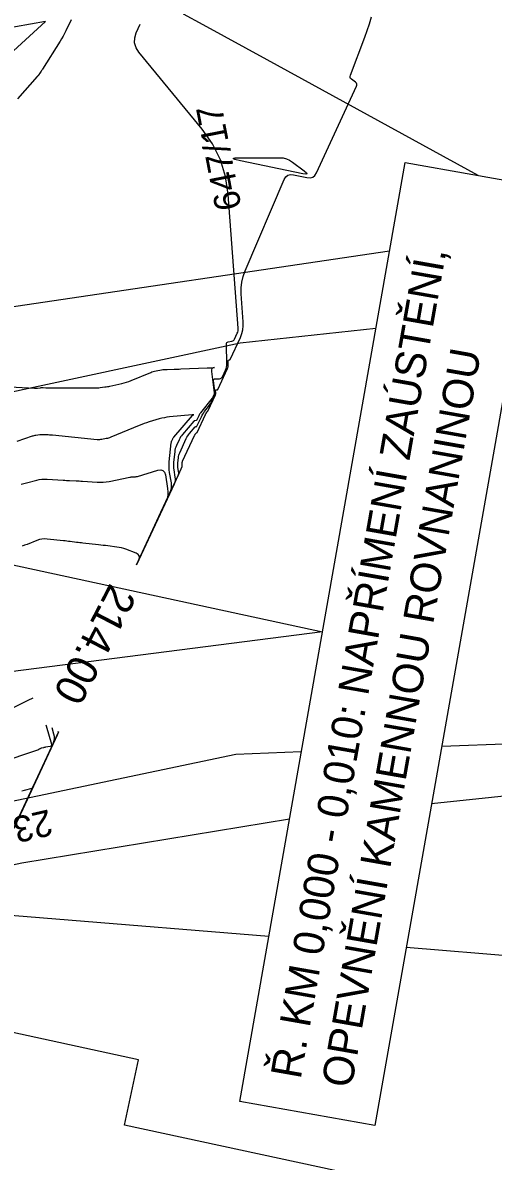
# Model space of a CAD drawing. Extents: x -534481 to -534256, y -1190577 to -1190138.
# Drawn here: x -534390.37 to -534375, y -1190542.27 to -1190505.1 of the extents above; entities that cross this region are included whole.
import ezdxf

# ---------------------------------------------------------------- set-up
doc = ezdxf.new("R2010")
doc.units = 0
for name, color, linetype in [('30', 7, 'Continuous'), ('31', 7, 'Continuous'), ('40', 7, 'Continuous'), ('_N_text', 7, 'Continuous'), ('Hranice parcel', 7, 'Continuous'), ('Parcelní čísla', 7, 'Continuous'), ('Polygon budovy', 7, 'Continuous')]:
    doc.layers.add(name, color=color, linetype=linetype)

msp = doc.modelspace()

# ---------------------------------------------------------------- linework, layer by layer
at = {"layer": '30'}
for points in [[(-534386.653, -1190522.8), (-534385.856, -1190521.088), (-534385.294, -1190519.882), (-534385.282, -1190519.85), (-534385.275, -1190519.818), (-534385.273, -1190519.786), (-534385.276, -1190519.752), (-534385.298, -1190519.617), (-534385.302, -1190519.583), (-534385.305, -1190519.549), (-534385.304, -1190519.515), (-534385.302, -1190519.481), (-534385.284, -1190519.303), (-534385.278, -1190519.263), (-534385.269, -1190519.223), (-534385.257, -1190519.184), (-534385.241, -1190519.146), (-534385.026, -1190518.68), (-534385.004, -1190518.636), (-534384.978, -1190518.594), (-534384.95, -1190518.554), (-534384.919, -1190518.515), (-534384.732, -1190518.299), (-534384.728, -1190518.295), (-534384.724, -1190518.292), (-534384.719, -1190518.29), (-534384.714, -1190518.289), (-534384.692, -1190518.286), (-534384.687, -1190518.285), (-534384.683, -1190518.282), (-534384.68, -1190518.279), (-534384.677, -1190518.275), (-534384.533, -1190517.965), (-534384.511, -1190517.92), (-534384.486, -1190517.878), (-534384.459, -1190517.836), (-534384.43, -1190517.796), (-534384.303, -1190517.636), (-534384.275, -1190517.598), (-534384.249, -1190517.559), (-534384.226, -1190517.519), (-534384.205, -1190517.477), (-534384.126, -1190517.306), (-534384.109, -1190517.263), (-534384.099, -1190517.219), (-534384.095, -1190517.174), (-534384.098, -1190517.128), (-534384.141, -1190516.797), (-534384.141, -1190516.767), (-534384.13, -1190516.746), (-534384.111, -1190516.732), (-534384.081, -1190516.728), (-534383.944, -1190516.725), (-534383.912, -1190516.72), (-534383.885, -1190516.708), (-534383.863, -1190516.688), (-534383.846, -1190516.661), (-534383.744, -1190516.442), (-534383.725, -1190516.394), (-534383.712, -1190516.345), (-534383.704, -1190516.296), (-534383.702, -1190516.244), (-534383.715, -1190515.597), (-534383.712, -1190515.569), (-534383.701, -1190515.548), (-534383.682, -1190515.532), (-534383.656, -1190515.523), (-534383.534, -1190515.499), (-534383.506, -1190515.49), (-534383.482, -1190515.476), (-534383.463, -1190515.456), (-534383.448, -1190515.431), (-534383.361, -1190515.243), (-534383.345, -1190515.202), (-534383.334, -1190515.16), (-534383.329, -1190515.116), (-534383.33, -1190515.072), (-534383.654, -1190510.714), (-534383.741, -1190510.128), (-534383.913, -1190509.577), (-534384.169, -1190509.059), (-534384.511, -1190508.575), (-534386.572, -1190506.067), (-534386.668, -1190505.918), (-534386.714, -1190505.761), (-534386.711, -1190505.598), (-534386.659, -1190505.429), (-534386.535, -1190505.149)], [(-534386.653, -1190522.8), (-534385.56, -1190520.454), (-534385.53, -1190520.375), (-534385.513, -1190520.294), (-534385.508, -1190520.211), (-534385.515, -1190520.126), (-534385.571, -1190519.785), (-534385.582, -1190519.699), (-534385.587, -1190519.614), (-534385.587, -1190519.528), (-534385.581, -1190519.442), (-534385.518, -1190518.819), (-534385.515, -1190518.802), (-534385.511, -1190518.785), (-534385.506, -1190518.769), (-534385.5, -1190518.753), (-534385.47, -1190518.69), (-534385.463, -1190518.674), (-534385.454, -1190518.659), (-534385.444, -1190518.645), (-534385.433, -1190518.632), (-534384.823, -1190517.927), (-534384.813, -1190517.918), (-534384.803, -1190517.91), (-534384.791, -1190517.905), (-534384.778, -1190517.902), (-534384.791, -1190517.904), (-534384.805, -1190517.906), (-534384.819, -1190517.907), (-534384.832, -1190517.909), (-534385.572, -1190517.975), (-534385.657, -1190517.985), (-534385.742, -1190517.998), (-534385.825, -1190518.016), (-534385.908, -1190518.038), (-534386.239, -1190518.135), (-534386.321, -1190518.161), (-534386.402, -1190518.188), (-534386.483, -1190518.218), (-534386.563, -1190518.25), (-534387.495, -1190518.637), (-534387.53, -1190518.651), (-534387.566, -1190518.663), (-534387.603, -1190518.673), (-534387.64, -1190518.681), (-534387.79, -1190518.709), (-534387.827, -1190518.715), (-534387.865, -1190518.718), (-534387.902, -1190518.718), (-534387.94, -1190518.716), (-534389.396, -1190518.573), (-534389.43, -1190518.57), (-534389.465, -1190518.567), (-534389.5, -1190518.565), (-534389.535, -1190518.563), (-534389.678, -1190518.556), (-534389.71, -1190518.555), (-534389.743, -1190518.556), (-534389.776, -1190518.558), (-534389.808, -1190518.561), (-534389.938, -1190518.577), (-534389.97, -1190518.581), (-534390.002, -1190518.588), (-534390.034, -1190518.596), (-534390.065, -1190518.606), (-534390.567, -1190518.78)], [(-534386.653, -1190522.8), (-534386.579, -1190522.641), (-534386.558, -1190522.57), (-534386.565, -1190522.511), (-534386.601, -1190522.463), (-534386.666, -1190522.426), (-534386.998, -1190522.296), (-534387.069, -1190522.271), (-534387.142, -1190522.25), (-534387.215, -1190522.234), (-534387.29, -1190522.222), (-534387.592, -1190522.184), (-534387.668, -1190522.175), (-534387.743, -1190522.166), (-534387.819, -1190522.157), (-534387.894, -1190522.149), (-534388.401, -1190522.093), (-534388.454, -1190522.087), (-534388.506, -1190522.081), (-534388.559, -1190522.075), (-534388.612, -1190522.068), (-534388.823, -1190522.043), (-534388.876, -1190522.036), (-534388.928, -1190522.03), (-534388.981, -1190522.024), (-534389.034, -1190522.018), (-534389.57, -1190521.961), (-534389.656, -1190521.957), (-534389.74, -1190521.963), (-534389.823, -1190521.979), (-534389.905, -1190522.006), (-534390.228, -1190522.134), (-534390.309, -1190522.164), (-534390.392, -1190522.192)], [(-534390.777, -1190527.517), (-534390.131, -1190527.193), (-534390.092, -1190527.174), (-534390.053, -1190527.154), (-534390.029, -1190527.142)], [(-534390.834, -1190531.775), (-534389.814, -1190529.586), (-534389.189, -1190528.244)], [(-534390.402, -1190530.184), (-534390.358, -1190530.174), (-534390.314, -1190530.163), (-534390.061, -1190530.097), (-534390.056, -1190530.096), (-534390.053, -1190530.093), (-534390.05, -1190530.09), (-534390.047, -1190530.086), (-534390.031, -1190530.05), (-534389.376, -1190528.644), (-534389.348, -1190528.567), (-534389.334, -1190528.49), (-534389.336, -1190528.41), (-534389.352, -1190528.33), (-534389.41, -1190528.129)]]:
    msp.add_lwpolyline(points, dxfattribs=at)
msp.add_lwpolyline([(-534381.105, -1190510.001), (-534381.089, -1190510.037), (-534381.127, -1190510.048), (-534381.217, -1190510.036), (-534383.254, -1190509.611), (-534383.437, -1190509.566), (-534383.496, -1190509.534), (-534383.431, -1190509.515), (-534383.243, -1190509.509), (-534381.981, -1190509.509), (-534381.865, -1190509.518), (-534381.755, -1190509.545), (-534381.651, -1190509.59), (-534381.553, -1190509.653), (-534381.173, -1190509.941)], close=True, dxfattribs=at)
at = {"layer": '31'}
for points in [[(-534388.782, -1190505.006), (-534388.96, -1190505.368), (-534389.004, -1190505.454), (-534389.05, -1190505.54), (-534389.098, -1190505.624), (-534389.149, -1190505.707), (-534389.725, -1190506.624), (-534389.734, -1190506.639), (-534389.743, -1190506.653), (-534389.753, -1190506.668), (-534389.762, -1190506.682), (-534389.806, -1190506.747), (-534389.813, -1190506.758), (-534389.82, -1190506.768), (-534389.828, -1190506.777), (-534389.835, -1190506.787), (-534389.866, -1190506.825), (-534389.874, -1190506.835), (-534389.882, -1190506.844), (-534389.89, -1190506.854), (-534389.898, -1190506.863), (-534390.536, -1190507.586)], [(-534386.653, -1190522.8), (-534385.274, -1190519.839), (-534385.161, -1190519.596), (-534385.158, -1190519.588), (-534385.156, -1190519.581), (-534385.156, -1190519.573), (-534385.156, -1190519.565), (-534385.162, -1190519.533), (-534385.163, -1190519.525), (-534385.163, -1190519.517), (-534385.163, -1190519.509), (-534385.163, -1190519.501), (-534385.158, -1190519.459), (-534385.157, -1190519.449), (-534385.155, -1190519.44), (-534385.152, -1190519.431), (-534385.148, -1190519.422), (-534384.759, -1190518.579), (-534384.753, -1190518.568), (-534384.747, -1190518.557), (-534384.74, -1190518.548), (-534384.732, -1190518.538), (-534384.686, -1190518.485), (-534384.683, -1190518.483), (-534384.675, -1190518.481), (-534384.673, -1190518.48), (-534384.673, -1190518.479), (-534384.399, -1190517.889), (-534384.394, -1190517.878), (-534384.387, -1190517.867), (-534384.38, -1190517.857), (-534384.373, -1190517.847), (-534384.342, -1190517.807), (-534384.334, -1190517.797), (-534384.328, -1190517.787), (-534384.321, -1190517.776), (-534384.316, -1190517.765), (-534384.075, -1190517.248), (-534384.07, -1190517.233), (-534384.066, -1190517.218), (-534384.065, -1190517.203), (-534384.066, -1190517.187), (-534384.076, -1190517.109), (-534384.076, -1190517.102), (-534384.073, -1190517.096), (-534384.068, -1190517.093), (-534384.06, -1190517.091), (-534384.025, -1190517.091), (-534384.017, -1190517.09), (-534384.01, -1190517.086), (-534384.004, -1190517.081), (-534384, -1190517.074), (-534383.681, -1190516.389), (-534383.671, -1190516.364), (-534383.664, -1190516.338), (-534383.66, -1190516.312), (-534383.659, -1190516.285), (-534383.662, -1190516.139), (-534383.661, -1190516.132), (-534383.658, -1190516.126), (-534383.653, -1190516.122), (-534383.646, -1190516.12), (-534383.614, -1190516.113), (-534383.606, -1190516.111), (-534383.6, -1190516.107), (-534383.595, -1190516.102), (-534383.591, -1190516.095), (-534383.258, -1190515.378), (-534383.21, -1190515.254), (-534383.179, -1190515.127), (-534383.164, -1190514.998), (-534383.165, -1190514.865), (-534383.233, -1190513.957), (-534383.236, -1190513.762), (-534383.216, -1190513.572), (-534383.173, -1190513.386), (-534383.107, -1190513.203), (-534381.832, -1190510.227), (-534381.78, -1190510.14), (-534381.711, -1190510.084), (-534381.626, -1190510.06), (-534381.525, -1190510.067), (-534381.086, -1190510.158), (-534380.984, -1190510.166), (-534380.898, -1190510.142), (-534380.827, -1190510.087), (-534380.772, -1190510.001), (-534379.465, -1190507.177), (-534379.454, -1190507.14), (-534379.455, -1190507.106), (-534379.47, -1190507.076), (-534379.497, -1190507.049), (-534379.631, -1190506.947), (-534379.659, -1190506.92), (-534379.674, -1190506.889), (-534379.677, -1190506.855), (-534379.668, -1190506.818), (-534379.196, -1190505.58), (-534379.116, -1190505.36), (-534379.041, -1190505.138), (-534378.973, -1190504.913)], [(-534391.592, -1190516.943), (-534389.984, -1190517.034), (-534389.96, -1190517.035), (-534389.935, -1190517.035), (-534389.911, -1190517.033), (-534389.887, -1190517.031), (-534389.787, -1190517.019), (-534389.765, -1190517.017), (-534389.743, -1190517.015), (-534389.721, -1190517.015), (-534389.699, -1190517.016), (-534389.61, -1190517.02), (-534389.588, -1190517.021), (-534389.565, -1190517.022), (-534389.543, -1190517.022), (-534389.521, -1190517.022), (-534388.006, -1190517.026), (-534387.966, -1190517.025), (-534387.925, -1190517.024), (-534387.884, -1190517.02), (-534387.844, -1190517.016), (-534387.683, -1190516.996), (-534387.642, -1190516.99), (-534387.602, -1190516.984), (-534387.562, -1190516.976), (-534387.523, -1190516.968), (-534387.133, -1190516.88), (-534387.055, -1190516.861), (-534386.979, -1190516.838), (-534386.903, -1190516.812), (-534386.829, -1190516.783), (-534386.19, -1190516.518), (-534386.147, -1190516.501), (-534386.104, -1190516.487), (-534386.06, -1190516.476), (-534386.015, -1190516.467), (-534385.834, -1190516.437), (-534385.788, -1190516.43), (-534385.743, -1190516.425), (-534385.697, -1190516.421), (-534385.651, -1190516.42), (-534385.419, -1190516.415), (-534385.365, -1190516.413), (-534385.311, -1190516.412), (-534385.257, -1190516.41), (-534385.203, -1190516.408), (-534384.341, -1190516.371), (-534384.281, -1190516.369), (-534384.221, -1190516.367), (-534384.162, -1190516.365), (-534384.102, -1190516.364), (-534384.153, -1190516.372), (-534384.188, -1190516.395), (-534384.205, -1190516.433), (-534384.206, -1190516.485), (-534384.114, -1190517.192), (-534384.113, -1190517.207), (-534384.115, -1190517.222), (-534384.118, -1190517.237), (-534384.124, -1190517.251), (-534384.15, -1190517.308), (-534384.157, -1190517.322), (-534384.165, -1190517.336), (-534384.173, -1190517.349), (-534384.183, -1190517.361), (-534384.559, -1190517.838), (-534384.576, -1190517.861), (-534384.591, -1190517.884), (-534384.605, -1190517.909), (-534384.618, -1190517.934), (-534384.681, -1190518.07), (-534384.686, -1190518.078), (-534384.692, -1190518.084), (-534384.699, -1190518.088), (-534384.708, -1190518.09), (-534384.746, -1190518.096), (-534384.755, -1190518.098), (-534384.763, -1190518.101), (-534384.771, -1190518.106), (-534384.777, -1190518.113), (-534385.152, -1190518.546), (-534385.184, -1190518.586), (-534385.214, -1190518.628), (-534385.24, -1190518.673), (-534385.264, -1190518.719), (-534385.351, -1190518.908), (-534385.371, -1190518.956), (-534385.387, -1190519.005), (-534385.398, -1190519.055), (-534385.405, -1190519.106), (-534385.441, -1190519.462), (-534385.446, -1190519.522), (-534385.446, -1190519.582), (-534385.442, -1190519.641), (-534385.434, -1190519.701), (-534385.396, -1190519.939), (-534385.39, -1190519.998), (-534385.394, -1190520.056), (-534385.406, -1190520.113), (-534385.427, -1190520.168), (-534386.653, -1190522.8)], [(-534390.417, -1190520.171), (-534390.333, -1190520.148), (-534390.248, -1190520.126), (-534389.912, -1190520.036), (-534389.827, -1190520.017), (-534389.742, -1190520.005), (-534389.656, -1190520), (-534389.569, -1190520.003), (-534389.048, -1190520.037), (-534388.996, -1190520.041), (-534388.943, -1190520.044), (-534388.891, -1190520.047), (-534388.838, -1190520.05), (-534388.628, -1190520.06), (-534388.576, -1190520.062), (-534388.523, -1190520.065), (-534388.471, -1190520.068), (-534388.418, -1190520.071), (-534387.938, -1190520.102), (-534387.841, -1190520.105), (-534387.744, -1190520.102), (-534387.648, -1190520.092), (-534387.551, -1190520.076), (-534386.871, -1190519.94), (-534386.851, -1190519.936), (-534386.83, -1190519.933), (-534386.809, -1190519.931), (-534386.788, -1190519.93), (-534386.704, -1190519.927), (-534386.684, -1190519.925), (-534386.663, -1190519.922), (-534386.643, -1190519.918), (-534386.622, -1190519.913), (-534385.959, -1190519.712), (-534385.862, -1190519.697), (-534385.788, -1190519.718), (-534385.736, -1190519.776), (-534385.707, -1190519.869), (-534385.635, -1190520.313), (-534385.625, -1190520.423), (-534385.631, -1190520.531), (-534385.654, -1190520.637), (-534385.694, -1190520.74), (-534386.653, -1190522.8)], [(-534389.613, -1190528.024), (-534389.606, -1190528.056), (-534389.43, -1190528.662), (-534389.426, -1190528.689), (-534389.432, -1190528.71), (-534389.448, -1190528.724), (-534389.474, -1190528.733), (-534389.629, -1190528.758), (-534389.645, -1190528.761), (-534389.661, -1190528.764), (-534389.677, -1190528.768), (-534389.693, -1190528.772), (-534389.766, -1190528.793), (-534389.777, -1190528.797), (-534389.788, -1190528.801), (-534389.798, -1190528.805), (-534389.808, -1190528.811), (-534389.849, -1190528.833), (-534389.859, -1190528.839), (-534389.87, -1190528.844), (-534389.88, -1190528.848), (-534389.891, -1190528.852), (-534391.16, -1190529.276)], [(-534391.016, -1190532.165), (-534389.189, -1190528.244)], [(-534389.218, -1190528.229), (-534389.217, -1190528.26), (-534389.227, -1190528.313), (-534389.246, -1190528.366), (-534390.653, -1190531.386)]]:
    msp.add_lwpolyline(points, dxfattribs=at)
at = {"layer": '_N_text'}
for p, q in [((-534405.885, -1190519.52), (-534380.58, -1190524.995)), ((-534380.58, -1190524.995), (-534411.965, -1190529.007))]:
    msp.add_line(p, q, dxfattribs=at)
msp.add_lwpolyline([(-534383.283, -1190540.324), (-534377.877, -1190509.666), (-534373.459, -1190510.445), (-534378.865, -1190541.103)], close=True, dxfattribs=at)
at = {"layer": 'Hranice parcel'}
for p, q in [((-534389.63, -1190505.06), (-534401.56, -1190515.98)), ((-534401.56, -1190515.98), (-534378.386, -1190512.549))]:
    msp.add_line(p, q, dxfattribs=at)
for points in [[(-534385.13, -1190504.81), (-534384.49, -1190505.16), (-534382.4, -1190506.3), (-534375.507, -1190510.084)], [(-534389.63, -1190505.06), (-534396.5, -1190506.28), (-534398.08, -1190506.56), (-534402.44, -1190507.34), (-534402.95, -1190507.61)], [(-534378.833, -1190515.085), (-534383.27, -1190515.56), (-534409.16, -1190521.11), (-534410.57, -1190521.41), (-534422.34, -1190523.93)], [(-534376.683, -1190528.726), (-534346.53, -1190527.59)], [(-534424.26, -1190537.56), (-534383.41, -1190528.98), (-534381.269, -1190528.899)], [(-534363.09, -1190529.14), (-534377.014, -1190530.603)], [(-534381.658, -1190531.109), (-534390.4, -1190532.54), (-534396.26, -1190533.8)], [(-534382.333, -1190534.934), (-534396.26, -1190533.8)], [(-534362.76, -1190542.27), (-534370.46, -1190535.9), (-534377.842, -1190535.299)]]:
    msp.add_lwpolyline(points, dxfattribs=at)
at = {"layer": 'Polygon budovy'}
msp.add_lwpolyline([(-534400.19, -1190541.92), (-534394.59, -1190543.13), (-534394.89, -1190544.51), (-534390.54, -1190545.47), (-534390.82, -1190546.76), (-534389.15, -1190547.11), (-534390.54, -1190553.66), (-534381.04, -1190555.72), (-534378.2, -1190543), (-534387.05, -1190541.1), (-534386.59, -1190538.96), (-534391.46, -1190537.91), (-534391.92, -1190540.05), (-534399.41, -1190538.44)], close=True, dxfattribs=at)

# ---------------------------------------------------------------- texts
at = {"layer": '40'}
msp.add_text('214.00', height=1, rotation=242.6092, dxfattribs=at).set_placement((-534387.51, -1190523.367))
at = {"layer": '_N_text'}
for s, p in [('Ř. KM 0,000 - 0,010: NAPŘÍMENÍ ZAÚSTĚNÍ, ', (-534381.294, -1190539.622)), ('OPEVNĚNÍ KAMENNOU ROVNANINOU', (-534379.632, -1190539.915))]:
    msp.add_text(s, height=1, rotation=80.0205, dxfattribs=at).set_placement(p)
at = {"layer": 'Parcelní čísla'}
for s, rotation, p in [('647/17', 101, (-534383.217, -1190511.145)), ('2302/512', 193, (-534389.518, -1190530.781))]:
    msp.add_text(s, height=0.85, rotation=rotation, dxfattribs=at).set_placement(p)

doc.saveas('drawing.dxf')
